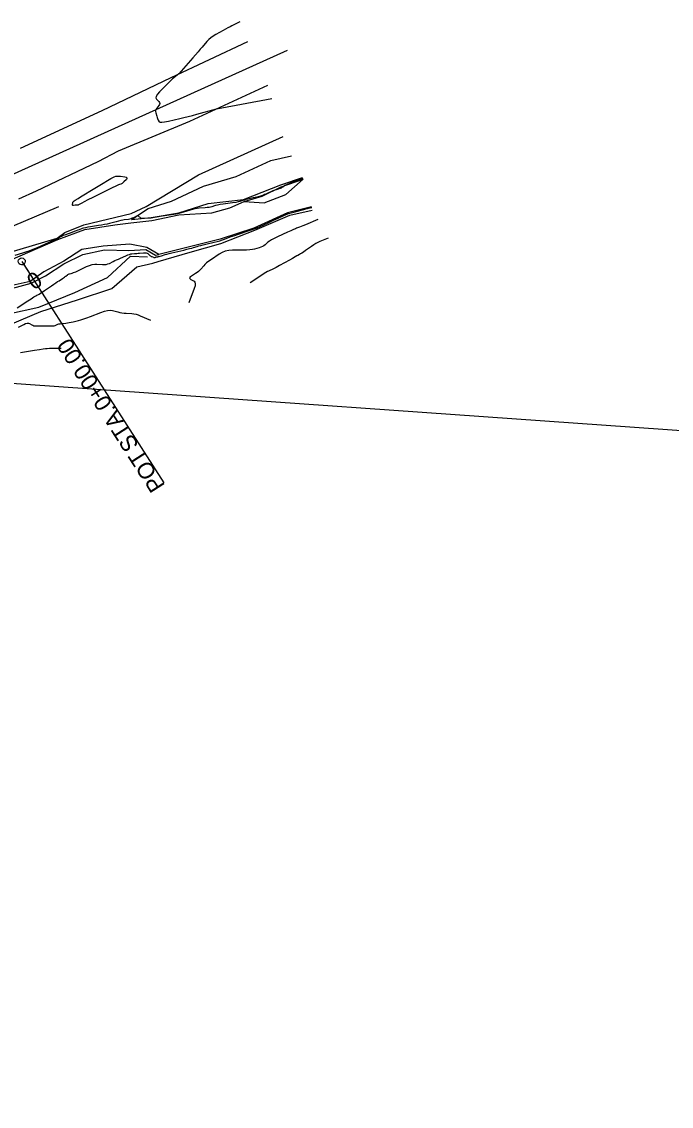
# Model space of a CAD drawing. Extents: x 2030588 to 2035216, y 462285 to 465007.
# Drawn here: x 2031383.7 to 2031494.9, y 464240.7 to 464426.2 of the extents above; entities that cross this region are included whole.
import ezdxf

# ---------------------------------------------------------------- set-up
doc = ezdxf.new("R2010")
doc.units = 0
for name, color, linetype in [('DT_X_Contour_Major', 7, 'Continuous'), ('DT_X_Contour_Minor', 7, 'Continuous'), ('DV_X_Property_Line', 7, 'Continuous'), ('GE_P_Alignment_100_Cardinal_Points', 7, 'Continuous'), ('GE_P_Alignment_100_Stations', 7, 'Continuous'), ('HY_X_Water_Edge', 7, 'Continuous'), ('PV_X_EOP', 7, 'Continuous'), ('RW_X_CL', 7, 'Continuous'), ('SV_X_Break_Lines', 7, 'Continuous'), ('SV_X_Toe_of_Slope', 7, 'Continuous'), ('SV_X_Top_of_Bank', 7, 'Continuous'), ('UT_X_Telecom', 7, 'Continuous')]:
    doc.layers.add(name, color=color, linetype=linetype)

msp = doc.modelspace()

# ---------------------------------------------------------------- linework, layer by layer
at = {"layer": 'DT_X_Contour_Major'}
for points in [[(2031436.18, 464389.22), (2031434.72, 464388.61), (2031434.39, 464388.46), (2031434.05, 464388.28), (2031433.69, 464388.06), (2031433.31, 464387.81), (2031432.27, 464387.08), (2031431.92, 464386.84), (2031431.64, 464386.64), (2031431.43, 464386.5), (2031431.28, 464386.42), (2031431, 464386.25), (2031430.83, 464386.16), (2031430.53, 464385.99), (2031430.09, 464385.75), (2031429.53, 464385.44), (2031427.84, 464384.51), (2031427.26, 464384.2), (2031426.82, 464383.97), (2031426.5, 464383.8), (2031426.3, 464383.71), (2031425.94, 464383.56), (2031425.77, 464383.48), (2031425.53, 464383.34), (2031425.21, 464383.14), (2031424.82, 464382.88), (2031422.84, 464381.56)], [(2031390.52, 464370.32), (2031389.76, 464370.31), (2031389.6, 464370.31), (2031389.46, 464370.31), (2031389.34, 464370.31), (2031389.24, 464370.31), (2031388.99, 464370.32), (2031388.88, 464370.32), (2031388.77, 464370.32), (2031388.64, 464370.32), (2031388.49, 464370.32), (2031388.09, 464370.3), (2031387.84, 464370.28), (2031387.4, 464370.22), (2031386.77, 464370.12), (2031385.95, 464369.99), (2031383.52, 464369.57)]]:
    msp.add_lwpolyline(points, dxfattribs=at)
at = {"layer": 'DT_X_Contour_Minor'}
for points in [[(2031421.05, 464426.24), (2031419.69, 464425.53), (2031419.38, 464425.36), (2031419.03, 464425.17), (2031418.63, 464424.96), (2031418.18, 464424.72), (2031416.94, 464424.05), (2031416.5, 464423.79), (2031416.09, 464423.5), (2031415.73, 464423.18), (2031415.41, 464422.84), (2031414.62, 464421.9), (2031414.29, 464421.52), (2031413.92, 464421.08), (2031413.49, 464420.59), (2031413.01, 464420.03), (2031410.64, 464417.31), (2031409.76, 464416.64), (2031409.54, 464416.46), (2031409.26, 464416.2), (2031408.92, 464415.86), (2031408.51, 464415.44), (2031407.34, 464414.23), (2031406.98, 464413.82), (2031406.76, 464413.47), (2031406.7, 464413.2), (2031406.78, 464413), (2031407.19, 464412.56), (2031407.31, 464412.39), (2031407.36, 464412.23), (2031407.33, 464412.06), (2031407.22, 464411.89), (2031406.84, 464411.44), (2031406.73, 464411.26), (2031406.66, 464411.07), (2031406.65, 464410.87), (2031406.69, 464410.65), (2031406.85, 464410.05), (2031406.92, 464409.84), (2031406.98, 464409.66), (2031407.04, 464409.51), (2031407.1, 464409.39), (2031407.27, 464409.11), (2031407.41, 464409.04), (2031407.72, 464409.04), (2031408.2, 464409.1), (2031408.84, 464409.24), (2031410.77, 464409.68), (2031411.5, 464409.85), (2031412.22, 464410.03), (2031412.95, 464410.22), (2031413.68, 464410.42), (2031417.08, 464411.35), (2031426.54, 464413.11)], [(2031431.85, 464399.39), (2031430.86, 464399.07), (2031430.64, 464398.99), (2031430.41, 464398.91), (2031430.18, 464398.82), (2031429.93, 464398.72), (2031428.75, 464398.21), (2031428.4, 464397.96), (2031428.32, 464397.91), (2031428.25, 464397.86), (2031428.18, 464397.82), (2031428.11, 464397.79), (2031427.93, 464397.72), (2031427.85, 464397.69), (2031427.74, 464397.66), (2031427.62, 464397.61), (2031427.47, 464397.56), (2031426.71, 464397.3), (2031425.71, 464396.83), (2031425.5, 464396.74), (2031425.29, 464396.65), (2031425.1, 464396.58), (2031424.91, 464396.51), (2031424.41, 464396.36), (2031424.21, 464396.29), (2031423.96, 464396.23), (2031423.67, 464396.16), (2031423.34, 464396.08), (2031422.41, 464395.87), (2031422.09, 464395.8), (2031421.83, 464395.73), (2031421.63, 464395.68), (2031421.5, 464395.63), (2031421.22, 464395.51), (2031421.06, 464395.46), (2031420.77, 464395.4), (2031420.36, 464395.33), (2031419.82, 464395.25), (2031418.23, 464395.03), (2031417.69, 464394.95), (2031417.25, 464394.87), (2031416.92, 464394.8), (2031416.7, 464394.74), (2031416.25, 464394.59), (2031416.05, 464394.53), (2031415.8, 464394.48), (2031415.5, 464394.44), (2031415.15, 464394.41), (2031414.13, 464394.32), (2031413.74, 464394.28), (2031413.35, 464394.21), (2031412.95, 464394.12), (2031412.55, 464394), (2031411.45, 464393.65), (2031411.04, 464393.53), (2031410.62, 464393.42), (2031410.19, 464393.33), (2031409.75, 464393.26), (2031408.58, 464393.07), (2031408.16, 464393.01), (2031407.78, 464392.95), (2031407.45, 464392.9), (2031407.16, 464392.85), (2031406.45, 464392.73), (2031406.18, 464392.69), (2031405.91, 464392.65), (2031405.65, 464392.63), (2031405.39, 464392.62), (2031404.17, 464392.57), (2031403.6, 464393.08), (2031402.85, 464392.69), (2031402.67, 464392.61), (2031402.47, 464392.54), (2031402.25, 464392.48), (2031402, 464392.43), (2031401.3, 464392.32), (2031401.02, 464392.28), (2031400.69, 464392.21), (2031400.33, 464392.12), (2031399.92, 464392.02), (2031398.78, 464391.73), (2031398.35, 464391.62), (2031397.89, 464391.52), (2031397.4, 464391.44), (2031396.9, 464391.35), (2031395.53, 464391.15), (2031395.05, 464391.07), (2031394.65, 464391), (2031394.34, 464390.92), (2031394.1, 464390.85), (2031393.57, 464390.64), (2031393.34, 464390.56), (2031393.06, 464390.45), (2031392.73, 464390.33), (2031392.34, 464390.19), (2031391.24, 464389.78), (2031390.87, 464389.64), (2031390.58, 464389.52), (2031390.37, 464389.43), (2031390.25, 464389.36), (2031390.04, 464389.2), (2031389.87, 464389.11), (2031389.54, 464388.95), (2031389.04, 464388.73), (2031388.37, 464388.44), (2031386.37, 464387.57), (2031385.65, 464387.27), (2031384.99, 464387.01), (2031384.41, 464386.79), (2031383.89, 464386.63), (2031382.59, 464386.24)], [(2031393.17, 464394.87), (2031393.12, 464394.87), (2031393.05, 464394.87), (2031392.97, 464394.86), (2031392.88, 464394.85), (2031392.6, 464394.81), (2031392.51, 464394.81), (2031392.45, 464394.83), (2031392.42, 464394.89), (2031392.43, 464394.98), (2031392.48, 464395.25), (2031392.52, 464395.36), (2031392.61, 464395.47), (2031392.73, 464395.58), (2031392.89, 464395.7), (2031393.38, 464396.02), (2031393.65, 464396.19), (2031394.08, 464396.45), (2031394.67, 464396.82), (2031395.43, 464397.27), (2031397.66, 464398.62), (2031398.41, 464399.06), (2031398.98, 464399.39), (2031399.36, 464399.6), (2031399.56, 464399.7), (2031399.86, 464399.79), (2031399.99, 464399.82), (2031400.17, 464399.83), (2031400.39, 464399.82), (2031400.65, 464399.79), (2031401.4, 464399.69), (2031401.63, 464399.63), (2031401.75, 464399.54), (2031401.75, 464399.42), (2031401.65, 464399.27), (2031401.22, 464398.82), (2031401.06, 464398.66), (2031400.93, 464398.55), (2031400.81, 464398.48), (2031400.72, 464398.44), (2031400.48, 464398.39), (2031400.28, 464398.32), (2031399.87, 464398.13), (2031399.25, 464397.83), (2031398.41, 464397.41), (2031395.89, 464396.16), (2031395.05, 464395.74), (2031394.42, 464395.43), (2031394.01, 464395.21), (2031393.81, 464395.1), (2031393.56, 464394.95), (2031393.47, 464394.9), (2031393.39, 464394.86), (2031393.33, 464394.84), (2031393.28, 464394.84), (2031393.17, 464394.87)], [(2031382.99, 464377.27), (2031384.79, 464378.46), (2031385.39, 464378.85), (2031385.85, 464379.15), (2031386.17, 464379.34), (2031386.34, 464379.44), (2031386.6, 464379.56), (2031386.74, 464379.63), (2031386.96, 464379.78), (2031387.27, 464379.98), (2031387.67, 464380.25), (2031388.84, 464381.06), (2031389.25, 464381.34), (2031389.6, 464381.58), (2031389.9, 464381.78), (2031390.14, 464381.93), (2031390.71, 464382.29), (2031390.91, 464382.42), (2031391.08, 464382.53), (2031391.21, 464382.63), (2031391.32, 464382.72), (2031391.57, 464382.94), (2031391.66, 464383.01), (2031391.76, 464383.07), (2031391.85, 464383.11), (2031391.95, 464383.13), (2031392.21, 464383.17), (2031392.36, 464383.21), (2031392.62, 464383.32), (2031392.99, 464383.47), (2031393.46, 464383.69), (2031394.85, 464384.34), (2031395.36, 464384.55), (2031395.81, 464384.7), (2031396.23, 464384.77), (2031396.61, 464384.78), (2031397.55, 464384.7), (2031397.89, 464384.69), (2031398.2, 464384.72), (2031398.49, 464384.79), (2031398.76, 464384.89), (2031399.42, 464385.23), (2031399.68, 464385.36), (2031399.97, 464385.5), (2031400.28, 464385.64), (2031400.62, 464385.79), (2031401.55, 464386.2), (2031401.88, 464386.34), (2031402.16, 464386.44), (2031402.4, 464386.51), (2031402.59, 464386.54), (2031403.05, 464386.57), (2031403.23, 464386.58), (2031403.44, 464386.6), (2031403.66, 464386.62), (2031403.91, 464386.64), (2031404.6, 464386.7), (2031404.84, 464386.7), (2031405.04, 464386.68), (2031405.2, 464386.63), (2031405.32, 464386.56), (2031405.59, 464386.31), (2031405.69, 464386.23), (2031405.79, 464386.16), (2031405.9, 464386.1), (2031406, 464386.05), (2031406.28, 464385.94), (2031406.37, 464385.91), (2031406.45, 464385.89), (2031406.51, 464385.89), (2031406.56, 464385.9), (2031406.66, 464385.96), (2031406.7, 464385.98), (2031406.75, 464386), (2031406.8, 464386.01), (2031406.86, 464386.02), (2031407.02, 464386.03), (2031407.11, 464386.05), (2031407.24, 464386.08), (2031407.42, 464386.13), (2031407.64, 464386.19), (2031408.3, 464386.39), (2031408.59, 464386.47), (2031408.96, 464386.57), (2031409.41, 464386.68), (2031409.95, 464386.81), (2031411.49, 464387.18), (2031412.02, 464387.31), (2031412.47, 464387.42), (2031412.84, 464387.52), (2031413.12, 464387.6), (2031413.75, 464387.79), (2031414.02, 464387.87), (2031414.37, 464387.96), (2031414.79, 464388.06), (2031415.27, 464388.18), (2031416.67, 464388.52), (2031417.18, 464388.65), (2031417.64, 464388.78), (2031418.07, 464388.91), (2031418.45, 464389.05), (2031419.43, 464389.41), (2031419.81, 464389.55), (2031420.22, 464389.69), (2031420.68, 464389.85), (2031421.16, 464390.01), (2031422.5, 464390.44), (2031423, 464390.61), (2031423.51, 464390.8), (2031424.02, 464391), (2031424.52, 464391.23), (2031425.88, 464391.85), (2031426.37, 464392.07), (2031426.82, 464392.28), (2031427.24, 464392.47), (2031427.62, 464392.65), (2031428.6, 464393.1), (2031428.98, 464393.26), (2031429.39, 464393.41), (2031429.83, 464393.55), (2031430.29, 464393.68), (2031431.57, 464394.02), (2031432.01, 464394.13), (2031432.35, 464394.22), (2031432.61, 464394.28), (2031432.78, 464394.32), (2031433.36, 464394.45)], [(2031434.38, 464392.4), (2031432.27, 464391.49), (2031431.86, 464391.32), (2031431.53, 464391.18), (2031431.28, 464391.08), (2031431.11, 464391.02), (2031430.75, 464390.9), (2031430.56, 464390.83), (2031430.23, 464390.69), (2031429.79, 464390.49), (2031429.22, 464390.22), (2031427.52, 464389.43), (2031426.94, 464389.15), (2031426.48, 464388.91), (2031426.12, 464388.69), (2031425.87, 464388.51), (2031425.37, 464388.08), (2031425.16, 464387.92), (2031424.93, 464387.79), (2031424.66, 464387.67), (2031424.37, 464387.57), (2031423.55, 464387.33), (2031423.2, 464387.25), (2031422.75, 464387.19), (2031422.22, 464387.16), (2031421.6, 464387.15), (2031419.81, 464387.15), (2031419.16, 464387.1), (2031418.56, 464386.98), (2031418.01, 464386.77), (2031417.5, 464386.48), (2031416.2, 464385.58), (2031415.75, 464385.26), (2031415.38, 464384.98), (2031415.09, 464384.72), (2031414.88, 464384.49), (2031414.41, 464383.93), (2031414.22, 464383.72), (2031414, 464383.53), (2031413.77, 464383.35), (2031413.5, 464383.17), (2031412.77, 464382.73), (2031412.56, 464382.57), (2031412.46, 464382.42), (2031412.49, 464382.29), (2031412.65, 464382.16), (2031413.22, 464381.85), (2031413.38, 464381.68), (2031413.44, 464381.41), (2031413.4, 464381.05), (2031413.25, 464380.58), (2031412.33, 464378.16)], [(2031383.18, 464374), (2031384.1, 464374.46), (2031384.42, 464374.6), (2031384.69, 464374.68), (2031384.91, 464374.69), (2031385.08, 464374.63), (2031385.47, 464374.38), (2031385.63, 464374.3), (2031385.82, 464374.24), (2031386.04, 464374.22), (2031386.27, 464374.21), (2031386.95, 464374.23), (2031387.21, 464374.24), (2031387.48, 464374.24), (2031387.75, 464374.24), (2031388.04, 464374.23), (2031388.83, 464374.21), (2031389.09, 464374.21), (2031389.31, 464374.22), (2031389.48, 464374.25), (2031389.59, 464374.3), (2031389.83, 464374.43), (2031389.94, 464374.48), (2031390.1, 464374.53), (2031390.31, 464374.56), (2031390.56, 464374.6), (2031391.3, 464374.68), (2031391.58, 464374.72), (2031391.89, 464374.77), (2031392.21, 464374.84), (2031392.56, 464374.92), (2031393.49, 464375.15), (2031393.88, 464375.26), (2031394.35, 464375.41), (2031394.89, 464375.6), (2031395.51, 464375.83), (2031397.27, 464376.51), (2031397.89, 464376.72), (2031398.43, 464376.84), (2031398.89, 464376.88), (2031399.28, 464376.83), (2031400.2, 464376.59), (2031400.54, 464376.51), (2031400.9, 464376.44), (2031401.25, 464376.4), (2031401.61, 464376.37), (2031402.58, 464376.33), (2031402.94, 464376.29), (2031403.31, 464376.21), (2031403.68, 464376.1), (2031404.04, 464375.95), (2031405.76, 464375.17)]]:
    msp.add_lwpolyline(points, dxfattribs=at)
at = {"layer": 'DV_X_Property_Line'}
msp.add_line((2033770.04, 464196.16), (2031006.37, 464390.79), dxfattribs=at)
at = {"layer": 'GE_P_Alignment_100_Cardinal_Points'}
msp.add_line((2031383.75, 464385.23), (2031408.07, 464347.37), dxfattribs=at)
msp.add_ellipse((2031383.75, 464385.23), major_axis=(-0.401, 0.446), ratio=0.999987, dxfattribs=at)
at = {"layer": 'GE_P_Alignment_100_Stations'}
msp.add_line((2031383.75, 464385.23), (2031384.83, 464383.54), dxfattribs=at)
at = {"layer": 'HY_X_Water_Edge'}
for points in [[(2031381.75, 464385.47), (2031389.93, 464389), (2031394.55, 464390.69), (2031399.7, 464391.51), (2031402.4, 464391.81), (2031406, 464392.21), (2031410.65, 464393.21), (2031416.25, 464393.53), (2031419.33, 464394.38), (2031421.78, 464395.47), (2031425.2, 464395.28), (2031428.93, 464396.69), (2031431.89, 464399.31)], [(2031433.34, 464394.58), (2031429.21, 464393.56), (2031423.43, 464390.93), (2031417.68, 464389.06), (2031412.68, 464387.77), (2031407.19, 464386.42), (2031405.17, 464387.64), (2031402.27, 464388.21), (2031397.71, 464387.83), (2031394.04, 464387.29), (2031390.93, 464385.29), (2031387.55, 464383.43), (2031385.21, 464381.82), (2031380.06, 464380.65)]]:
    msp.add_lwpolyline(points, dxfattribs=at)
at = {"layer": 'PV_X_EOP'}
for points in [[(2031422.36, 464422.77), (2031409.23, 464416.65), (2031397.45, 464411.01), (2031383.47, 464404.56)], [(2031383.24, 464395.95), (2031386.29, 464397.3), (2031396.84, 464402.33), (2031400.31, 464404.12), (2031412.52, 464409.25), (2031425.83, 464415.38)]]:
    msp.add_lwpolyline(points, dxfattribs=at)
at = {"layer": 'RW_X_CL'}
msp.add_line((2031247.01, 464338.98), (2031429.22, 464421.39), dxfattribs=at)
at = {"layer": 'SV_X_Break_Lines'}
msp.add_line((2031406.62, 464386.28), (2031407.19, 464386.42), dxfattribs=at)
for points in [[(2031402.53, 464392.38), (2031405.4, 464394.27), (2031409.37, 464395.56), (2031414.87, 464398.09), (2031420.45, 464399.78), (2031426.35, 464402.52), (2031429.91, 464403.28)], [(2031419.33, 464394.38), (2031421.78, 464395.47), (2031424.86, 464396.38), (2031428.15, 464398.01), (2031431.89, 464399.31)], [(2031363.4, 464369.64), (2031366.32, 464372.12), (2031369.42, 464374.11), (2031372.14, 464376.61), (2031375.73, 464377.32), (2031380.1, 464380.07), (2031385.36, 464381.49), (2031387.8, 464382.74), (2031390.96, 464384.84), (2031394.2, 464386.41), (2031397.91, 464387.19), (2031402.07, 464387.12), (2031404.99, 464387.29), (2031406.62, 464386.28)]]:
    msp.add_lwpolyline(points, dxfattribs=at)
at = {"layer": 'SV_X_Toe_of_Slope'}
msp.add_lwpolyline([(2031363.4, 464369.64), (2031367.12, 464370.8), (2031370.34, 464372.98), (2031373.07, 464374.08), (2031376.76, 464375), (2031381.48, 464376.26), (2031386.69, 464377.4), (2031392.83, 464379.91), (2031398.44, 464382.48), (2031402.36, 464386.14), (2031405.27, 464386.04)], dxfattribs=at)
at = {"layer": 'SV_X_Top_of_Bank'}
for points in [[(2031343.66, 464369.09), (2031346.18, 464371.92), (2031348.83, 464372.84), (2031353.63, 464374.38), (2031358.14, 464375.72), (2031362.34, 464378.46), (2031364.4, 464379.79), (2031367.73, 464381.96), (2031370.07, 464382.78), (2031372.14, 464383.06), (2031376.29, 464385.1), (2031379.09, 464386.17), (2031381.38, 464386.72), (2031389.79, 464389.22), (2031391.15, 464390.2), (2031394.4, 464391.5), (2031402.5, 464393.41), (2031405.06, 464394.63), (2031413.97, 464400.02), (2031428.45, 464406.61)], [(2031402.53, 464392.38), (2031405.88, 464392.77), (2031410.62, 464393.57), (2031415.67, 464395.15), (2031421.68, 464395.83), (2031428.08, 464398.32), (2031431.77, 464399.58)], [(2031347.65, 464357.55), (2031349.64, 464359.11), (2031351.52, 464360.69), (2031352.63, 464362.11), (2031353.83, 464363.7), (2031356.5, 464365.04), (2031361.05, 464367.16), (2031364.06, 464368.6), (2031368.2, 464369.16), (2031373.94, 464372.28), (2031377.97, 464373.27), (2031381.75, 464374.45), (2031387.05, 464376.66), (2031393.31, 464378.67), (2031399.17, 464380.6), (2031403.43, 464384.28), (2031406.17, 464384.91), (2031407.07, 464385.2), (2031412.57, 464386.8), (2031417.79, 464388.29), (2031423.62, 464390.55), (2031429.62, 464393.17), (2031433.45, 464394.01)]]:
    msp.add_lwpolyline(points, dxfattribs=at)
at = {"layer": 'UT_X_Telecom'}
msp.add_lwpolyline([(2031285.42, 464261.06), (2031282.83, 464263.07), (2031280.24, 464267.27), (2031278.64, 464271.13), (2031276.62, 464283.19), (2031273.03, 464315.33), (2031271.84, 464326.16), (2031274.51, 464334.07), (2031278.51, 464339.42), (2031283.38, 464343.38), (2031302.41, 464353.61), (2031313.88, 464359.38), (2031348, 464374.28), (2031378.36, 464389.66), (2031390.12, 464394.61)], dxfattribs=at)

# ---------------------------------------------------------------- texts
at = {"layer": 'GE_P_Alignment_100_Cardinal_Points'}
for s, p in [('0+00.00', (2031399.34, 464360.88)), (' STA. ', (2031404.45, 464352.93)), ('POT', (2031408.34, 464346.88))]:
    msp.add_text(s, height=2.8, rotation=122.7248, dxfattribs=at).set_placement(p)
at = {"layer": 'GE_P_Alignment_100_Stations'}
msp.add_text('0', height=2.8, rotation=212.7245, dxfattribs=at).set_placement((2031386.04, 464383.72))

doc.saveas('drawing.dxf')
